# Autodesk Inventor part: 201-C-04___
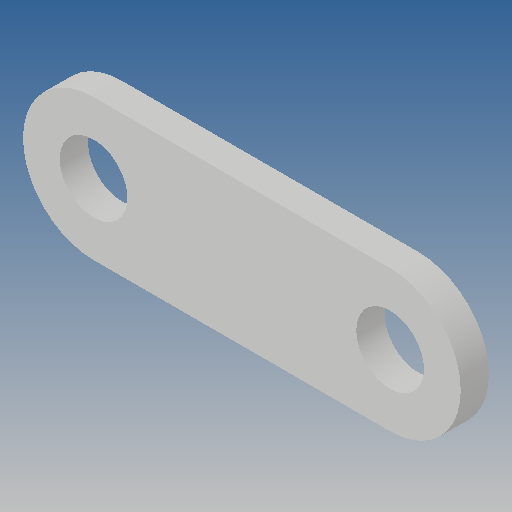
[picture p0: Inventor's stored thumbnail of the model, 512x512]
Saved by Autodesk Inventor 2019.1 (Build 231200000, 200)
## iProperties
Created: 2010-06
Part Number: 201-C-04___
Material: Ogólny
Document SubType Name: Modeling
Designer: CADENGINEERING4
Density: 1 g/cm^3
Appearance: Domyślna
Author: CADENGINEERING4
Revision Number: ANY
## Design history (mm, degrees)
feature "NONE"
node "Bryła1"
